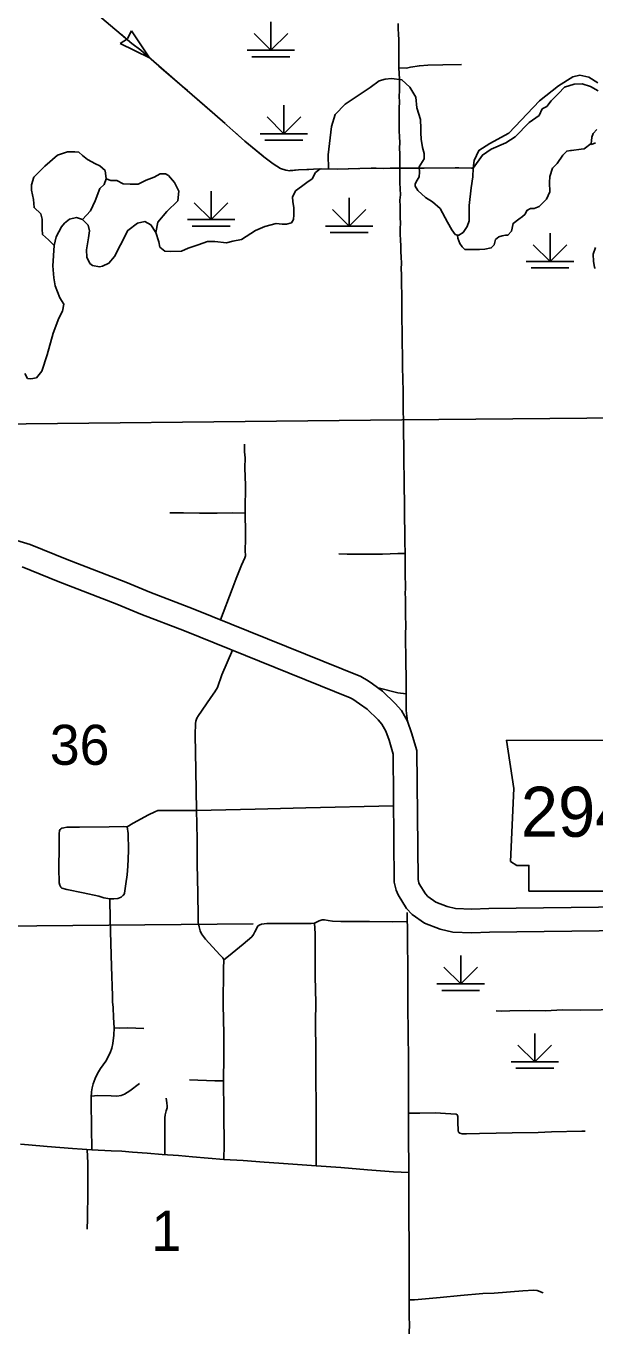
# Model space of a CAD drawing. Extents: x 1127717 to 1741049, y 2026793 to 2244711.
# Drawn here: x 1301075 to 1307075, y 2097463 to 2111217 of the extents above; entities that cross this region are included whole.
import ezdxf

# ---------------------------------------------------------------- set-up
doc = ezdxf.new("R2010")
doc.units = 0
for name, color, linetype in [('10', 7, 'Continuous'), ('21', 7, 'Continuous'), ('31', 7, 'Continuous'), ('32', 7, 'Continuous'), ('35', 7, 'Continuous'), ('4', 7, 'Continuous'), ('43', 7, 'Continuous'), ('44', 7, 'Continuous'), ('5', 7, 'Continuous')]:
    doc.layers.add(name, color=color, linetype=linetype)

msp = doc.modelspace()

# ---------------------------------------------------------------- linework, layer by layer
at = {"layer": '10'}
for points in [[(1299881, 2106117), (1301118, 2105748), (1301507, 2105589), (1302127, 2105351), (1302380, 2105245), (1302838, 2105071), (1304606, 2104356), (1304683, 2104310), (1304729, 2104279), (1304834, 2104202), (1304969, 2104072), (1305034, 2103997), (1305098, 2103884), (1305141, 2103760), (1305197, 2103576), (1305209, 2102213), (1305216, 2102178), (1305221, 2102168), (1305287, 2102062), (1305312, 2102035), (1305396, 2101976), (1305517, 2101928), (1305606, 2101908), (1305775, 2101903), (1305957, 2101909), (1308559, 2101941)], [(1308564, 2101691), (1305962, 2101659), (1305775, 2101653), (1305575, 2101659), (1305443, 2101689), (1305277, 2101755), (1305147, 2101846), (1305087, 2101910), (1304998, 2102052), (1304977, 2102103), (1304959, 2102185), (1304947, 2103538), (1304903, 2103683), (1304870, 2103780), (1304829, 2103852), (1304788, 2103900), (1304673, 2104010), (1304593, 2104068), (1304521, 2104116), (1304494, 2104132), (1302747, 2104838), (1302287, 2105013), (1302034, 2105119), (1301415, 2105357), (1301035, 2105511)]]:
    msp.add_lwpolyline(points, dxfattribs=at)
at = {"layer": '21'}
msp.add_lwpolyline([(1306142, 2103683), (1306218, 2103175), (1306184, 2102405), (1306252, 2102363), (1306379, 2102363), (1306379, 2102092), (1307445, 2102092), (1307496, 2102202), (1307479, 2102380), (1307504, 2102583), (1307597, 2102744), (1307656, 2102862), (1307741, 2102989), (1307792, 2103124), (1307834, 2103234), (1307910, 2103327), (1307927, 2103386), (1307893, 2103429), (1307631, 2103429), (1307690, 2103547), (1307699, 2103623), (1307663, 2103682)], close=True, dxfattribs=at)
at = {"layer": '31'}
for points in [[(1305023, 2109138), (1305022, 2109198), (1305021, 2109259), (1305020, 2109319), (1305018, 2109381), (1305023, 2109438), (1305022, 2109499), (1305018, 2109562), (1305017, 2109623), (1305018, 2109683), (1305018, 2109744), (1305017, 2109806), (1305016, 2109868), (1305015, 2109929), (1305016, 2109988), (1305014, 2110050), (1305011, 2110111), (1305010, 2110171), (1305009, 2110236), (1305011, 2110290), (1305011, 2110354), (1305014, 2110415), (1305011, 2110476), (1305013, 2110535), (1305012, 2110596), (1305012, 2110657), (1305011, 2110718), (1305008, 2110777), (1305006, 2110837), (1305006, 2110897), (1305005, 2110956), (1305005, 2111015), (1305005, 2111072), (1305004, 2111130), (1305001, 2111187), (1305000, 2111243)], [(1305098, 2103884), (1305085, 2103998), (1305084, 2104029), (1305084, 2104062), (1305084, 2104096), (1305083, 2104131), (1305083, 2104166), (1305084, 2104201), (1305085, 2104238), (1305084, 2104278), (1305084, 2104318), (1305084, 2104360), (1305083, 2104403), (1305082, 2104447), (1305082, 2104491), (1305080, 2104536), (1305080, 2104581), (1305080, 2104628), (1305077, 2104677), (1305077, 2104726), (1305077, 2104775), (1305077, 2104824), (1305081, 2104870), (1305080, 2104921), (1305078, 2104972), (1305076, 2105023), (1305076, 2105074), (1305076, 2105126), (1305077, 2105178), (1305072, 2105234), (1305076, 2105285), (1305076, 2105340), (1305075, 2105396), (1305075, 2105453), (1305072, 2105513), (1305072, 2105570), (1305072, 2105629), (1305072, 2105687), (1305071, 2105746), (1305070, 2105806), (1305070, 2105866), (1305069, 2105927), (1305068, 2105989), (1305067, 2106052), (1305066, 2106115), (1305066, 2106178), (1305065, 2106242), (1305064, 2106307), (1305063, 2106371), (1305063, 2106435), (1305062, 2106499), (1305061, 2106563), (1305061, 2106628), (1305060, 2106692), (1305059, 2106756), (1305058, 2106821), (1305057, 2106886), (1305056, 2106950), (1305056, 2107014), (1305055, 2107078), (1305054, 2107141), (1305054, 2107204), (1305053, 2107268), (1305052, 2107332), (1305051, 2107396), (1305049, 2107460), (1305048, 2107524), (1305046, 2107587), (1305044, 2107654), (1305045, 2107714), (1305044, 2107777), (1305043, 2107841), (1305042, 2107904), (1305042, 2107967), (1305041, 2108030), (1305040, 2108092), (1305039, 2108155), (1305038, 2108219), (1305038, 2108282), (1305037, 2108345), (1305037, 2108408), (1305036, 2108471), (1305034, 2108533), (1305033, 2108595), (1305031, 2108657), (1305033, 2108716), (1305030, 2108778), (1305028, 2108838), (1305027, 2108898), (1305023, 2108960), (1305020, 2109021), (1305021, 2109080), (1305023, 2109138)], [(1303125, 2104955), (1303248, 2105276), (1303292, 2105391), (1303349, 2105530), (1303382, 2105607), (1303388, 2105628), (1303387, 2105685), (1303389, 2105804), (1303388, 2105949), (1303387, 2106000), (1303387, 2106110), (1303388, 2106369), (1303383, 2106558), (1303387, 2106662), (1303383, 2106694), (1303378, 2106725), (1303380, 2106778), (1303379, 2106808)], [(1303386, 2106078), (1303257, 2106082), (1303089, 2106079), (1302906, 2106079), (1302737, 2106082), (1302593, 2106083)], [(1305072, 2105654), (1304997, 2105652), (1304836, 2105646), (1304674, 2105646), (1304461, 2105646), (1304375, 2105648)], [(1302872, 2102942), (1302866, 2103366), (1302859, 2103740), (1302862, 2103860), (1302866, 2103884), (1302876, 2103915), (1302893, 2103944), (1302926, 2103991), (1302986, 2104078), (1303050, 2104168), (1303066, 2104193), (1303093, 2104239), (1303141, 2104373), (1303254, 2104633)], [(1304789, 2104235), (1304995, 2104185), (1305083, 2104174)], [(1302872, 2102942), (1302683, 2102942), (1302494, 2102942), (1302465, 2102941), (1302434, 2102928), (1302365, 2102898), (1302206, 2102809), (1302141, 2102771)], [(1304952, 2102993), (1304027, 2102969), (1303493, 2102955), (1302872, 2102942)], [(1303161, 2099261), (1303164, 2099416), (1303160, 2099743), (1303159, 2100115), (1303160, 2100321), (1303160, 2100585), (1303155, 2100892), (1303156, 2101272), (1303160, 2101368), (1303151, 2101389), (1303118, 2101419), (1302967, 2101584), (1302924, 2101640), (1302912, 2101671), (1302900, 2101715), (1302891, 2101759), (1302889, 2101824), (1302888, 2102067), (1302879, 2102378), (1302879, 2102631), (1302875, 2102803), (1302872, 2102942)], [(1302141, 2102771), (1302104, 2102773), (1301951, 2102771), (1301640, 2102767), (1301505, 2102766), (1301474, 2102761), (1301454, 2102757), (1301442, 2102750), (1301435, 2102743), (1301428, 2102730), (1301425, 2102697), (1301424, 2102554), (1301422, 2102333), (1301425, 2102180), (1301430, 2102156), (1301441, 2102133), (1301451, 2102124), (1301505, 2102108), (1301679, 2102072), (1301841, 2102038), (1301894, 2102022), (1301957, 2102012), (1302000, 2102011), (1302044, 2102015), (1302077, 2102028), (1302094, 2102044), (1302107, 2102054), (1302113, 2102070), (1302126, 2102167), (1302140, 2102262), (1302150, 2102356), (1302151, 2102429), (1302154, 2102525), (1302151, 2102700), (1302141, 2102771)], [(1301957, 2102012), (1301961, 2101787), (1301977, 2101297), (1301985, 2100988), (1301987, 2100924), (1301995, 2100864), (1301997, 2100760), (1302004, 2100649), (1302000, 2100572), (1301991, 2100483), (1301980, 2100436), (1301961, 2100386), (1301917, 2100298), (1301861, 2100221), (1301829, 2100169), (1301803, 2100115), (1301783, 2100058), (1301772, 2100018), (1301766, 2099973), (1301762, 2099913), (1301763, 2099889), (1301765, 2099575), (1301770, 2099391), (1301770, 2099364)], [(1305115, 2097423), (1305118, 2097531), (1305117, 2097586), (1305116, 2097641), (1305116, 2097696), (1305115, 2097750), (1305115, 2097804), (1305116, 2097858), (1305116, 2097913), (1305117, 2097967), (1305117, 2098023), (1305116, 2098078), (1305116, 2098134), (1305116, 2098189), (1305116, 2098245), (1305115, 2098301), (1305114, 2098358), (1305114, 2098416), (1305114, 2098474), (1305113, 2098533), (1305112, 2098592), (1305112, 2098651), (1305112, 2098710), (1305112, 2098769), (1305112, 2098828), (1305112, 2098887), (1305112, 2098946), (1305112, 2099006), (1305113, 2099065), (1305113, 2099125), (1305112, 2099184), (1305111, 2099244), (1305111, 2099303), (1305110, 2099362), (1305110, 2099422), (1305109, 2099483), (1305109, 2099543), (1305109, 2099604), (1305109, 2099665), (1305108, 2099727), (1305108, 2099787), (1305108, 2099848), (1305107, 2099908), (1305108, 2099967), (1305108, 2100027), (1305108, 2100086), (1305107, 2100144), (1305107, 2100202), (1305107, 2100259), (1305107, 2100315), (1305107, 2100372), (1305107, 2100428), (1305106, 2100485), (1305106, 2100541), (1305105, 2100597), (1305104, 2100654), (1305103, 2100822), (1305103, 2101164), (1305103, 2101222), (1305103, 2101279), (1305102, 2101335), (1305102, 2101390), (1305099, 2101446), (1305099, 2101494), (1305099, 2101546), (1305099, 2101617), (1305098, 2101670), (1305098, 2101724), (1305096, 2101771), (1305096, 2101821), (1305096, 2101866)], [(1303160, 2101368), (1303211, 2101404), (1303364, 2101533), (1303457, 2101611), (1303473, 2101634), (1303489, 2101663), (1303518, 2101723), (1303532, 2101734), (1303558, 2101744), (1303616, 2101749), (1303743, 2101749), (1303944, 2101750), (1304082, 2101750), (1304118, 2101755), (1304168, 2101778), (1304197, 2101788), (1304222, 2101789), (1304262, 2101782), (1304306, 2101776), (1304394, 2101772), (1304696, 2101770), (1304936, 2101768), (1305096, 2101771)], [(1304136, 2099192), (1304136, 2099361), (1304134, 2099768), (1304131, 2100181), (1304131, 2100393), (1304129, 2100711), (1304132, 2100914), (1304123, 2101192), (1304124, 2101494), (1304123, 2101645), (1304118, 2101755)], [(1302318, 2100644), (1302150, 2100648), (1302058, 2100647), (1302004, 2100649)], [(1302273, 2100063), (1302170, 2099984), (1302114, 2099948), (1302077, 2099935), (1302031, 2099929), (1301971, 2099932), (1301832, 2099934), (1301763, 2099928)], [(1302539, 2099319), (1302537, 2099404), (1302537, 2099700), (1302542, 2099733), (1302552, 2099775), (1302563, 2099806), (1302564, 2099824), (1302560, 2099858), (1302554, 2099907)], [(1305113, 2099125), (1304949, 2099132), (1304675, 2099153), (1304394, 2099175), (1304136, 2099192), (1303740, 2099221), (1303587, 2099233), (1303366, 2099250), (1303161, 2099261), (1302832, 2099288), (1302682, 2099302), (1302511, 2099314), (1302352, 2099327), (1302198, 2099338), (1302084, 2099347), (1301974, 2099352), (1301770, 2099364), (1301564, 2099377), (1301298, 2099398), (1301102, 2099415), (1301015, 2099421)]]:
    msp.add_lwpolyline(points, dxfattribs=at)
at = {"layer": '32'}
for points in [[(1305666, 2110812), (1305472, 2110807), (1305311, 2110805), (1305224, 2110798), (1305131, 2110782), (1305087, 2110774), (1305008, 2110777)], [(1307245, 2100843), (1307140, 2100841), (1306927, 2100835), (1306734, 2100838), (1306552, 2100830), (1306386, 2100831), (1306179, 2100829), (1306085, 2100825), (1306033, 2100829)], [(1303159, 2100089), (1303065, 2100092), (1302798, 2100102)], [(1305108, 2099751), (1305227, 2099750), (1305391, 2099752), (1305555, 2099743), (1305611, 2099738), (1305623, 2099733), (1305627, 2099726), (1305630, 2099715), (1305630, 2099654), (1305631, 2099566), (1305637, 2099549), (1305651, 2099538), (1305673, 2099532), (1305721, 2099532), (1305858, 2099536), (1306033, 2099539), (1306202, 2099542), (1306477, 2099547), (1306616, 2099552), (1306938, 2099560), (1306971, 2099560)], [(1301720, 2099367), (1301725, 2099221), (1301727, 2098935), (1301722, 2098624), (1301721, 2098535), (1301719, 2098524)], [(1306529, 2097853), (1306467, 2097878), (1306429, 2097883), (1306314, 2097876), (1306012, 2097849), (1305894, 2097848), (1305656, 2097827), (1305441, 2097804), (1305173, 2097781), (1305115, 2097780)]]:
    msp.add_lwpolyline(points, dxfattribs=at)
at = {"layer": '35'}
for points in [[(1304265, 2109710), (1304260, 2109859), (1304295, 2110159), (1304334, 2110286), (1304439, 2110394), (1304704, 2110568), (1304800, 2110638), (1304861, 2110656), (1304930, 2110664), (1305039, 2110651), (1305122, 2110573), (1305187, 2110468), (1305196, 2110355), (1305235, 2110233), (1305239, 2110138), (1305239, 2110090), (1305243, 2110024), (1305256, 2109937), (1305274, 2109872), (1305274, 2109816), (1305222, 2109733)], [(1305791, 2109719), (1305800, 2109800), (1305849, 2109906), (1305967, 2109978), (1306168, 2110087), (1306491, 2110427), (1306689, 2110588), (1306842, 2110683), (1306917, 2110698), (1307009, 2110677), (1307104, 2110617)], [(1305791, 2109719), (1305889, 2109857), (1305981, 2109920), (1306134, 2109987), (1306235, 2110047), (1306381, 2110200), (1306488, 2110274), (1306519, 2110344), (1306568, 2110369), (1306614, 2110427), (1306689, 2110505), (1306755, 2110574), (1306856, 2110605), (1306940, 2110608), (1307029, 2110580), (1307109, 2110534)], [(1307095, 2110125), (1307055, 2110084), (1307043, 2110044), (1307037, 2110007), (1307035, 2109978), (1307040, 2109969), (1307081, 2109984)], [(1307035, 2109978), (1306960, 2109921), (1306931, 2109918), (1306827, 2109903), (1306816, 2109903), (1306778, 2109898), (1306735, 2109857), (1306678, 2109768), (1306629, 2109719), (1306600, 2109630), (1306597, 2109567), (1306600, 2109469), (1306563, 2109391), (1306488, 2109313), (1306433, 2109293), (1306396, 2109293), (1306358, 2109273), (1306338, 2109233), (1306312, 2109207), (1306272, 2109181), (1306212, 2109135), (1306194, 2109054), (1306157, 2109011), (1306131, 2109011), (1306097, 2109005), (1306062, 2108994), (1306027, 2108965), (1306013, 2108910), (1305981, 2108876), (1305912, 2108864), (1305858, 2108861), (1305809, 2108861), (1305763, 2108859), (1305728, 2108861), (1305702, 2108861), (1305676, 2108887), (1305651, 2108925), (1305630, 2108979), (1305625, 2109010)], [(1301671, 2109176), (1301753, 2109268), (1301804, 2109373), (1301854, 2109504), (1301900, 2109546), (1301921, 2109605), (1301909, 2109693), (1301854, 2109744), (1301808, 2109765), (1301724, 2109811), (1301669, 2109853), (1301631, 2109887), (1301589, 2109891), (1301513, 2109891), (1301408, 2109857), (1301274, 2109740), (1301156, 2109622), (1301131, 2109542), (1301131, 2109487), (1301152, 2109386), (1301160, 2109302), (1301231, 2109235), (1301244, 2109180), (1301244, 2109125), (1301244, 2109075), (1301248, 2109020), (1301311, 2108961), (1301372, 2108902)], [(1302444, 2109041), (1302464, 2109150), (1302561, 2109260), (1302675, 2109373), (1302687, 2109474), (1302641, 2109567), (1302578, 2109639), (1302544, 2109660), (1302489, 2109660), (1302426, 2109622), (1302342, 2109592), (1302258, 2109550), (1302174, 2109550), (1302098, 2109554), (1302031, 2109588), (1301968, 2109588), (1301921, 2109605)], [(1303495, 2109062), (1303592, 2109104), (1303714, 2109134), (1303777, 2109129), (1303823, 2109129), (1303874, 2109142), (1303895, 2109176), (1303899, 2109226), (1303899, 2109298), (1303890, 2109365), (1303886, 2109411), (1303916, 2109479), (1303979, 2109525), (1304038, 2109567), (1304092, 2109605), (1304126, 2109672), (1304176, 2109710)], [(1305222, 2109733), (1305225, 2109677), (1305221, 2109628), (1305201, 2109591), (1305180, 2109553), (1305180, 2109529), (1305207, 2109482), (1305288, 2109409), (1305361, 2109362), (1305442, 2109291), (1305519, 2109150), (1305564, 2109068), (1305602, 2109020), (1305625, 2109010), (1305641, 2109010), (1305685, 2109038), (1305726, 2109101), (1305750, 2109162), (1305750, 2109206), (1305748, 2109243), (1305750, 2109326), (1305769, 2109510), (1305787, 2109626), (1305791, 2109719)], [(1301062, 2107551), (1301091, 2107501), (1301125, 2107496), (1301184, 2107505), (1301243, 2107576), (1301298, 2107749), (1301360, 2107976), (1301419, 2108136), (1301461, 2108208), (1301473, 2108283), (1301431, 2108351), (1301381, 2108477), (1301368, 2108561), (1301356, 2108687), (1301372, 2108902), (1301393, 2108995), (1301448, 2109100), (1301482, 2109138), (1301532, 2109180), (1301608, 2109197), (1301671, 2109176), (1301730, 2109117), (1301743, 2109058), (1301734, 2108982), (1301713, 2108856), (1301717, 2108780), (1301747, 2108713), (1301776, 2108692), (1301848, 2108679), (1301881, 2108683), (1301949, 2108717), (1302008, 2108788), (1302071, 2108910), (1302147, 2109062), (1302251, 2109138), (1302327, 2109155), (1302390, 2109121), (1302444, 2109041), (1302474, 2108940), (1302486, 2108885), (1302537, 2108843), (1302596, 2108839), (1302714, 2108843), (1302785, 2108873), (1302890, 2108910), (1302987, 2108944), (1303067, 2108944), (1303189, 2108932), (1303256, 2108948), (1303349, 2108965), (1303495, 2109062)], [(1307081, 2108882), (1307055, 2108810), (1307058, 2108735), (1307069, 2108674), (1307078, 2108660)]]:
    msp.add_lwpolyline(points, dxfattribs=at)
at = {"layer": '4'}
msp.add_lwpolyline([(1300042, 2101714), (1303471, 2101747)], dxfattribs=at)
at = {"layer": '43'}
for p, q in [((1302186, 2111167), (1302146, 2111085)), ((1302377, 2110882), (1302186, 2111167)), ((1302145, 2111084), (1302069, 2111033)), ((1302069, 2111033), (1302377, 2110882))]:
    msp.add_line(p, q, dxfattribs=at)
for points in [[(1301694, 2111451), (1302192, 2111033), (1302285, 2110962), (1302720, 2110584), (1303066, 2110286), (1303383, 2110003), (1303584, 2109839), (1303682, 2109765), (1303758, 2109713), (1303816, 2109696), (1303858, 2109691), (1303949, 2109702), (1304038, 2109705), (1304176, 2109710), (1304359, 2109707), (1304595, 2109715), (1304767, 2109719), (1304840, 2109713), (1304915, 2109719), (1305099, 2109719), (1305274, 2109717), (1305600, 2109721), (1305791, 2109719)], [(1302072, 2111134), (1302192, 2111033), (1302285, 2110962), (1302377, 2110882)], [(1302477, 2110795), (1302720, 2110584), (1302776, 2110536)], [(1302876, 2110449), (1303066, 2110286), (1303174, 2110189)], [(1303273, 2110101), (1303383, 2110003), (1303575, 2109846)], [(1303681, 2109766), (1303682, 2109765), (1303758, 2109713), (1303816, 2109696), (1303858, 2109691), (1303859, 2109692)], [(1303859, 2109692), (1303949, 2109702), (1304038, 2109705), (1304057, 2109705)], [(1304189, 2109710), (1304359, 2109707), (1304584, 2109715)], [(1304716, 2109718), (1304767, 2109719), (1304840, 2109713), (1304915, 2109719), (1305099, 2109719), (1305112, 2109719)], [(1305244, 2109717), (1305274, 2109717), (1305600, 2109721), (1305640, 2109720)], [(1305772, 2109719), (1305791, 2109719)]]:
    msp.add_lwpolyline(points, dxfattribs=at)
at = {"layer": '44'}
for p, q in [((1303658, 2111262), (1303658, 2110962)), ((1303658, 2110962), (1303481, 2111139)), ((1303658, 2110962), (1303835, 2111139)), ((1303408, 2110962), (1303908, 2110962)), ((1303458, 2110894), (1303858, 2110894)), ((1303795, 2110382), (1303795, 2110082)), ((1303795, 2110082), (1303619, 2110259)), ((1303795, 2110082), (1303972, 2110259)), ((1303545, 2110082), (1304045, 2110082)), ((1303595, 2110014), (1303995, 2110014)), ((1303026, 2109475), (1303026, 2109175)), ((1304482, 2109406), (1304482, 2109106)), ((1303026, 2109175), (1302849, 2109352)), ((1303026, 2109175), (1303203, 2109352)), ((1304482, 2109106), (1304306, 2109283)), ((1304482, 2109106), (1304659, 2109283)), ((1302776, 2109175), (1303276, 2109175)), ((1302826, 2109107), (1303226, 2109107)), ((1304232, 2109106), (1304732, 2109106)), ((1304282, 2109038), (1304682, 2109038)), ((1306601, 2109033), (1306601, 2108733)), ((1306601, 2108733), (1306424, 2108910)), ((1306601, 2108733), (1306778, 2108910)), ((1306351, 2108733), (1306851, 2108733)), ((1306401, 2108665), (1306801, 2108665)), ((1305659, 2101412), (1305659, 2101112)), ((1305659, 2101112), (1305482, 2101289)), ((1305659, 2101112), (1305836, 2101289)), ((1305409, 2101112), (1305909, 2101112)), ((1305459, 2101044), (1305859, 2101044)), ((1306440, 2100591), (1306440, 2100291)), ((1306440, 2100291), (1306263, 2100468)), ((1306440, 2100291), (1306616, 2100468)), ((1306190, 2100291), (1306690, 2100291)), ((1306240, 2100223), (1306640, 2100223))]:
    msp.add_line(p, q, dxfattribs=at)
at = {"layer": '5'}
for points in [[(1299752, 2107006), (1305040, 2107063)], [(1305040, 2107063), (1311280, 2107120)]]:
    msp.add_lwpolyline(points, dxfattribs=at)

# ---------------------------------------------------------------- texts
at = {"layer": '21'}
msp.add_text('294', height=528, dxfattribs=at).set_placement((1306293, 2102665))
at = {"layer": '5'}
for s, height, p in [('36', 422.4, (1301326, 2103424)), ('1', 422, (1302397, 2098297))]:
    msp.add_text(s, height=height, dxfattribs=at).set_placement(p)

doc.saveas('drawing.dxf')
